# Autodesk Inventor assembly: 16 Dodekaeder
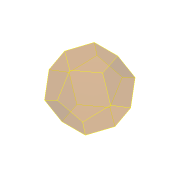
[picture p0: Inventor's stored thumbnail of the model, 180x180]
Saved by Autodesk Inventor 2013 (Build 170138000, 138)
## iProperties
Created: 2012-10
Part Number: 16 Dodekaeder
Document SubType Name: Assembly
Designer: Administrator
Author: Administrator
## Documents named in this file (2)
- C:\_ARBEIT\Dropbox\_Firma\Schulungen\IV_Grundlagen\Inventor Grundkörper\16 Dodekaeder.iam
- C:\_ARBEIT\Dropbox\_Firma\Schulungen\IV_Grundlagen\Inventor Grundkörper\16 Dodekaeder.ipt
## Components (12 placed, 1 different names)
1. 16 Dodekaeder:1 — Passend:1, Passend:2, Passend:3, Passend:5, Passend:7, Passend:9
2. 16 Dodekaeder:2 — Passend:3, Passend:4
3. 16 Dodekaeder:3 — Passend:1, Passend:2, Passend:4, Passend:6, Passend:11, Passend:15
4. 16 Dodekaeder:4 — Passend:5, Passend:6, Passend:8, Passend:12, Passend:14
5. 16 Dodekaeder:5 — Passend:7, Passend:8, Passend:10, Passend:17
6. 16 Dodekaeder:6 — Passend:9, Passend:10, Passend:19
7. 16 Dodekaeder:7 — Passend:11, Passend:12, Passend:13, Passend:16
8. 16 Dodekaeder:8 — Passend:13, Passend:14, Passend:18, Passend:22
9. 16 Dodekaeder:9 — Passend:15, Passend:16
10. 16 Dodekaeder:10 — Passend:17, Passend:18, Passend:20, Passend:21
11. 16 Dodekaeder:11 — Passend:19, Passend:20
12. 16 Dodekaeder:12 — Passend:21, Passend:22
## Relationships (22: Mate 22)
- Passend:1 [Mate]: 16 Dodekaeder:1 ↔ 16 Dodekaeder:3
- Passend:2 [Mate]: 16 Dodekaeder:1 ↔ 16 Dodekaeder:3
- Passend:3 [Mate]: 16 Dodekaeder:1 ↔ 16 Dodekaeder:2
- Passend:4 [Mate]: 16 Dodekaeder:2 ↔ 16 Dodekaeder:3
- Passend:5 [Mate]: 16 Dodekaeder:1 ↔ 16 Dodekaeder:4
- Passend:6 [Mate]: 16 Dodekaeder:3 ↔ 16 Dodekaeder:4
- Passend:7 [Mate]: 16 Dodekaeder:1 ↔ 16 Dodekaeder:5
- Passend:8 [Mate]: 16 Dodekaeder:4 ↔ 16 Dodekaeder:5
- Passend:9 [Mate]: 16 Dodekaeder:1 ↔ 16 Dodekaeder:6
- Passend:10 [Mate]: 16 Dodekaeder:5 ↔ 16 Dodekaeder:6
- Passend:11 [Mate]: 16 Dodekaeder:3 ↔ 16 Dodekaeder:7
- Passend:12 [Mate]: 16 Dodekaeder:4 ↔ 16 Dodekaeder:7
- Passend:13 [Mate]: 16 Dodekaeder:7 ↔ 16 Dodekaeder:8
- Passend:14 [Mate]: 16 Dodekaeder:4 ↔ 16 Dodekaeder:8
- Passend:15 [Mate]: 16 Dodekaeder:3 ↔ 16 Dodekaeder:9
- Passend:16 [Mate]: 16 Dodekaeder:7 ↔ 16 Dodekaeder:9
- Passend:17 [Mate]: 16 Dodekaeder:5 ↔ 16 Dodekaeder:10
- Passend:18 [Mate]: 16 Dodekaeder:8 ↔ 16 Dodekaeder:10
- Passend:19 [Mate]: 16 Dodekaeder:6 ↔ 16 Dodekaeder:11
- Passend:20 [Mate]: 16 Dodekaeder:10 ↔ 16 Dodekaeder:11
- Passend:21 [Mate]: 16 Dodekaeder:10 ↔ 16 Dodekaeder:12
- Passend:22 [Mate]: 16 Dodekaeder:8 ↔ 16 Dodekaeder:12
